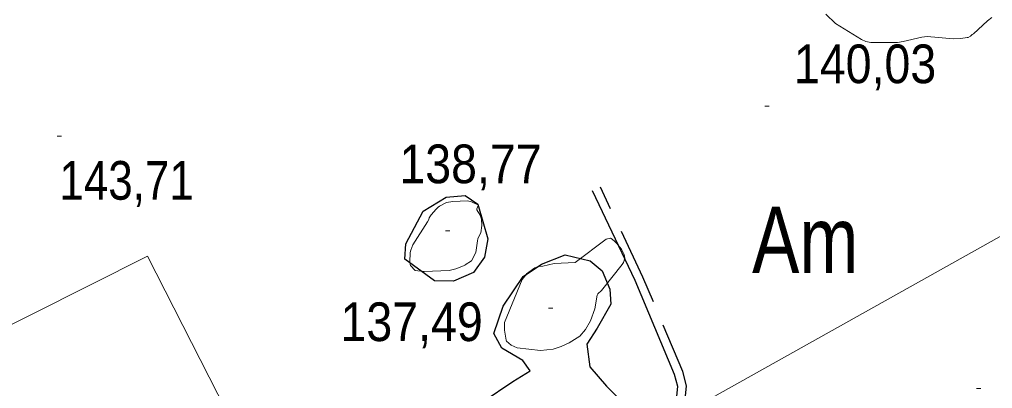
# Model space of a CAD drawing. Extents: x 480269 to 484877, y 4383588 to 4386804.
# Drawn here: x 481183 to 481403.4, y 4385711.2 to 4385794.6 of the extents above; entities that cross this region are included whole.
import ezdxf
from ezdxf.enums import TextEntityAlignment as Align

# ---------------------------------------------------------------- set-up
doc = ezdxf.new("R2010")
doc.units = 0
doc.header["$LTSCALE"] = 3.8
doc.linetypes.add('LONG_DASHED', pattern=[7.5, 6, -1.5])
doc.linetypes.add('MEDIUM_DASHED', pattern=[4.5, 3, -1.5])
for name, color, linetype, lineweight in [('25', 7, 'LONG_DASHED', 25), ('38', 7, 'Continuous', 25), ('51', 7, 'Continuous', 13), ('7', 7, 'Continuous', 13), ('9', 7, 'Continuous', 13)]:
    doc.layers.add(name, color=color, linetype=linetype, lineweight=lineweight)
doc.layers.add('31', color=7, linetype='Continuous')

msp = doc.modelspace()

# ---------------------------------------------------------------- linework, layer by layer
at = {"layer": '25'}
msp.add_lwpolyline([(481285.82, 4385737.39), (481281.3, 4385735.43), (481276.99, 4385735.51), (481270.29, 4385740.46), (481270.48, 4385743.89), (481274.41, 4385751.3), (481279.61, 4385754.48), (481283.96, 4385754.84), (481286.78, 4385752.9), (481289.05, 4385745.01), (481288.3, 4385740.87)], close=True, dxfattribs=at)
msp.add_lwpolyline([(481287.99, 4385708.26), (481294.76, 4385712.74), (481298.63, 4385715.2), (481297.03, 4385717.5), (481292.26, 4385720.27), (481290.44, 4385723.58), (481292.52, 4385729.78), (481297.07, 4385736.51), (481301.26, 4385739.29), (481306.62, 4385741.4), (481312.26, 4385740.05), (481314.97, 4385737.75), (481316.74, 4385733.65), (481316.91, 4385730.25), (481313.83, 4385724.82), (481311.47, 4385721.23), (481312.17, 4385716.1), (481315.94, 4385711.72), (481318.79, 4385708.82)], dxfattribs=at)
at = {"layer": '38'}
msp.add_lwpolyline([(481384.18, 4385582.04), (481378.36, 4385590.83), (481353.77, 4385644.5), (481334.78, 4385686.23), (481327.3, 4385701.6), (481328.97, 4385705.86), (481331.86, 4385709.47), (481332.11, 4385711.66), (481331.37, 4385714.36), (481322.43, 4385735.57), (481312.8, 4385755.89)], dxfattribs=at)
at = {"layer": '38', "linetype": 'MEDIUM_DASHED'}
msp.add_lwpolyline([(481385.58, 4385583.45), (481380.07, 4385591.77), (481355.54, 4385645.31), (481336.54, 4385687.06), (481329.42, 4385701.68), (481330.67, 4385704.88), (481333.73, 4385708.69), (481334.09, 4385711.81), (481333.21, 4385715), (481324.21, 4385736.37), (481314.56, 4385756.73)], dxfattribs=at)
at = {"layer": '51'}
for points in [[(481500.9, 4385674.38), (481487.81, 4385665.19), (481439.05, 4385764.51), (481334.13, 4385705.9)], [(481040.57, 4385655), (481212.01, 4385741.07), (481237.94, 4385690.35), (481262.67, 4385703.78), (481272.45, 4385685.99)]]:
    msp.add_lwpolyline(points, dxfattribs=at)
at = {"layer": '7'}
for p, q in [((481351.77, 4385775), (481352.77, 4385775)), ((481191.58, 4385768.24), (481192.58, 4385768.24)), ((481279.47, 4385746.86), (481280.47, 4385746.86)), ((481302.82, 4385729.32), (481303.82, 4385729.32)), ((481399.73, 4385711.18), (481400.73, 4385711.18))]:
    msp.add_line(p, q, dxfattribs=at)
at = {"layer": '9'}
for points in [[(481365.64, 4385795.82), (481367.79, 4385793.72), (481373.72, 4385790.09), (481374.68, 4385789.65), (481375.78, 4385789.44), (481381.82, 4385789.44), (481383.14, 4385789.63), (481387.32, 4385790.66)], [(481387.32, 4385790.66), (481388.58, 4385790.75), (481394.5, 4385790.26), (481396.15, 4385790.3), (481397.62, 4385790.52), (481397.84, 4385790.58), (481398.36, 4385790.82), (481398.77, 4385791.21), (481399.03, 4385791.38), (481402.25, 4385794.34), (481403.18, 4385795.09)]]:
    msp.add_lwpolyline(points, dxfattribs=at)
for points in [[(481279.74, 4385753.27), (481281.14, 4385753.48), (481284.5, 4385753.6), (481285.07, 4385753.49), (481285.41, 4385753.37), (481286.96, 4385752.63), (481286.94, 4385752.56), (481286.71, 4385752.16), (481286.59, 4385751.79), (481286.6, 4385751.68), (481286.62, 4385751.58), (481286.83, 4385751.19), (481287.12, 4385750.77), (481287.26, 4385750.52), (481287.65, 4385749.5), (481287.67, 4385749.4), (481287.66, 4385749.3), (481287.74, 4385748.16), (481287.74, 4385748.05), (481287.49, 4385746.4), (481287.11, 4385745.7), (481286.85, 4385745.04), (481286.74, 4385744.56), (481286.38, 4385741.93), (481285.36, 4385740.05), (481283.94, 4385739.13), (481283.93, 4385739.11), (481283.92, 4385739.1), (481281.87, 4385738.25), (481280.32, 4385737.89), (481274.66, 4385737.66), (481274.66, 4385737.64), (481274.65, 4385737.61), (481274.49, 4385737.61), (481272.6, 4385737.84), (481271.54, 4385739.02), (481271.52, 4385739.12), (481271.41, 4385740.16), (481271.49, 4385741.54), (481271.47, 4385741.72), (481271.46, 4385741.89), (481271.47, 4385741.96), (481271.61, 4385742.45), (481272.12, 4385743.65), (481275.44, 4385748.84), (481275.71, 4385749.43), (481275.81, 4385749.76), (481275.93, 4385749.98), (481276.27, 4385750.47), (481277.36, 4385751.73), (481277.85, 4385752.16), (481278.17, 4385752.39)], [(481301.04, 4385719.77), (481295.73, 4385720.41), (481294.38, 4385720.97), (481293.32, 4385721.9), (481293.25, 4385722.11), (481292.82, 4385724.39), (481292.83, 4385726.12), (481296.84, 4385735.83), (481297.83, 4385737.06), (481297.85, 4385737.08), (481299.71, 4385738.43), (481300.09, 4385738.61), (481300.71, 4385738.75), (481301.55, 4385738.86), (481304.12, 4385739.47), (481308.85, 4385739.7), (481315.91, 4385744.93), (481316.82, 4385745.19), (481317.24, 4385744.94), (481317.85, 4385744.45), (481318.24, 4385744.05), (481319.31, 4385742.69), (481319.74, 4385741.93), (481319.92, 4385741.46), (481320.12, 4385740.66), (481319.76, 4385739.67), (481319.5, 4385739.24), (481314.85, 4385733.33), (481313.96, 4385732.57), (481313.9, 4385732.45), (481313.85, 4385732.29), (481313.28, 4385729.22), (481312.32, 4385726.5), (481311.23, 4385724.5), (481309.91, 4385723.04), (481309.9, 4385723.03), (481309.89, 4385723.03), (481307.48, 4385721.5), (481305.71, 4385720.65), (481303.91, 4385720.07)]]:
    msp.add_lwpolyline(points, close=True, dxfattribs=at)

# ---------------------------------------------------------------- texts
at = {"layer": '31', "width": 0.8}
msp.add_text('Am', height=15, dxfattribs=at).set_placement((481360.95, 4385737.31), align=Align.CENTER)
at = {"layer": '7'}
for s, width, p in [('140,03', 0.9, (481358.39, 4385780.22)), ('138,77', 0.9, (481269.05, 4385757.6)), ('143,71', 0.85, (481192.08, 4385753.87)), ('137,49', 0.9, (481255.72, 4385721.9))]:
    msp.add_text(s, height=8.75, dxfattribs=dict(at, width=width)).set_placement(p)

doc.saveas('drawing.dxf')
